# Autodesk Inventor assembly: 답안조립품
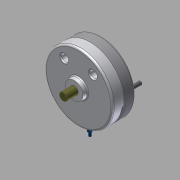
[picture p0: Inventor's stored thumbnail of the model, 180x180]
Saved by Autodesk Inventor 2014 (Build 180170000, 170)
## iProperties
Created: 2015-06
Part Number: 답안조립품
Document SubType Name: Assembly
Designer: MYHOME
Author: MYHOME
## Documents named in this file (9)
- C:\Documents and Settings\MYHOME\바탕 화면\450631V1036\답안조립품.iam
- C:\Documents and Settings\MYHOME\바탕 화면\450631V1036\본체.ipt
- C:\Documents and Settings\MYHOME\바탕 화면\450631V1036\덮개.ipt
- C:\Documents and Settings\MYHOME\바탕 화면\450631V1036\축.ipt
- C:\Documents and Settings\MYHOME\바탕 화면\450631V1036\베어링62_22.ipt
- C:\Documents and Settings\MYHOME\바탕 화면\450631V1036\멈춤링.ipt
- C:\Documents and Settings\MYHOME\바탕 화면\450631V1036\슬라이더2.ipt
- C:\Documents and Settings\MYHOME\바탕 화면\450631V1036\슬라이더.ipt
- C:\Documents and Settings\MYHOME\바탕 화면\450631V1036\M10x35.ipt
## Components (6 placed, 3 different names)
1. KS B 2023 62/22 - 22 x 50 x 14:1
2. KS B 2023 62/22 - 22 x 50 x 14:2
3. KS B 1336 22 x 1.2:1
4. KS B 1336 22 x 1.2:2
5. KS B 1003 - 미터 M 10 x 35:1
6. KS B 1003 - 미터 M 10 x 35:2
